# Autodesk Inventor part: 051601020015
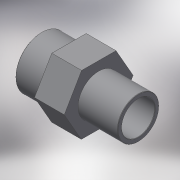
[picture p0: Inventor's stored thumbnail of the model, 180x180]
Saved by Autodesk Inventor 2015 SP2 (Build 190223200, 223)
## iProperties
Created: 2017-10
Part Number: 051601020015
Material: Generic
Description: PLASSON THR. REDUCING NIPPLE 2"-1.1/2" PVC
Document SubType Name: Modeling
Designer: KIM
Density: 1 g/cm^3
Appearance: Default
Author: KIM
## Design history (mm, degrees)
derived "051601.ipt"
feature "Solid1::051601.ipt"
tag "TaggingFeature1"
body "Solid1"
other parameters: "d0" = 64, "d2" = 65, "d13" = 0, "d14" = 0.47803, "d17" = 22, "d18" = 31.2, "d19" = 59.614, "d21" = 47.803, "d23" = 47.6912, "d24" = 38.2424, "d25" = 26, "d26" = -22, "R_1" = 47.803, "C_" = 65, "lt_1" = 22, "lt_" = 26, "H_" = 64, "R_" = 59.614
